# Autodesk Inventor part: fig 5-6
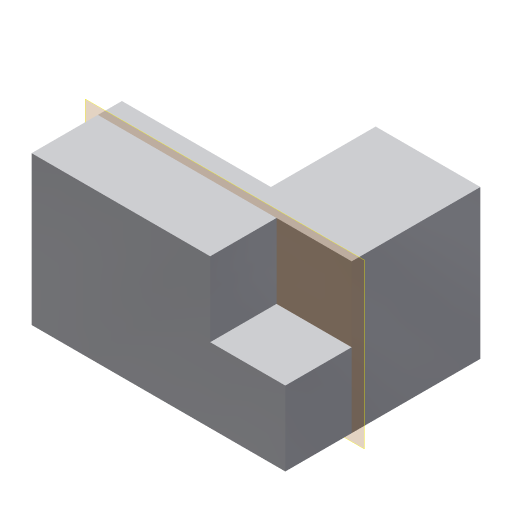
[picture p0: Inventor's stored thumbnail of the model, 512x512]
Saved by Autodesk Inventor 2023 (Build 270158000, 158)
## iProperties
Created: 2010-02
Part Number: fig 5-6
Document SubType Name: Modeling
Designer: CADSoft
Density: 1 g/cm^3
Material: Generic
Appearance: Default
Author: CADSoft
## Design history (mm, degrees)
sketch "Sketch1"
  geometry: L1 (0, 26.227)-(0, 12.145); L2 (0, 12.145)-(-20.026, 12.145); L3 (-20.026, 12.145)-(-20.026, 0); L4 (-20.026, 0)-(14.083, 0); L5 (14.083, 0)-(14.083, 26.227); L6 (14.083, 26.227)-(0, 26.227); 1 further point
  constraints: 12 end point
extrude "Extrusion1" new body sketch "Sketch1" distance "d0" = 20; taper "d1" = 0 deg
sketch "Sketch2"
  geometry: L1 (14.083, 0)-(3.983, 0); L2 (3.983, 0)-(3.983, 8.922); L3 (3.983, 8.922)-(14.083, 8.922); L4 (14.083, 8.922)-(14.083, 0); 1 further point
  constraints: 8 end point
extrude "Extrusion2" cut sketch "Sketch2" distance "d2" = 10; taper "d3" = 0 deg
workplane "Work Plane1"
body "Solid1"
